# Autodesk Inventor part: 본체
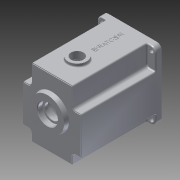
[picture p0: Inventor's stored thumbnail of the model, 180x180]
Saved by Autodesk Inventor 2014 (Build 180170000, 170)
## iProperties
Created: 2016-02
Part Number: 본체
Material: 알루미늄 6061
Document SubType Name: Modeling
Designer: mduedu
Density: 2.71 g/cm^3
Appearance: 알루미늄 - 평지
Author: mduedu
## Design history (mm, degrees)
sketch "스케치1"
  geometry: L1 (-47, -47)-(47, -47); L2 (47, -47)-(47, 63); L3 (47, 63)-(-47, 63); L4 (-47, 63)-(-47, -47); 2 further points
  constraints: 8 end point, 2 parallel, 1 horizontal, 1 midpoint, 1 perpendicular, 1 vertical alignment
  dimensions: "d0" = 94 distance of L2.end L3.end; "d155" = 110 distance of L1.end L2.end; "d156" = 47 distance from line of L1 point (0, 0)
extrude "돌출1" new body sketch "스케치1" distance "d2" = 130; taper "d3" = 0 deg
sketch "스케치3"
  geometry: C1 r 40 at (0, 0); 1 further point
  constraints: 1 centre point, 1 coincident
  dimensions: "d9" = 80 diameter of C1
extrude "돌출3" cut sketch "스케치3" distance "d11" = 121; taper "d12" = 0 deg
sketch "스케치4"
  geometry: C1 r 21 at (0, 11); 1 further point
  constraints: 1 centre point, 1 vertical alignment
  dimensions: "d13" = 21 radius of C1; "d15" = 11 distance of point (0, 0) C1.centre
extrude "돌출4" join sketch "스케치4" distance "d16" = 7; taper "d17" = 0 deg
sketch "스케치5"
  geometry: C1 r 15 at (0, -20); 1 further point
  constraints: 1 centre point, 1 vertical alignment
  dimensions: "d18" = 15 radius of C1; "d20" = 20 distance of point (0, 0) C1.centre
extrude "돌출5" join sketch "스케치5" distance "d21" = 7; taper "d22" = 0 deg
sketch "스케치6"
  geometry: C1 r 28 at (0, 11); A1 r 21 centre (0, 11) between (8.978, -7.984) and (-8.978, -7.984) reference; 1 further point
  constraints: 1 centre point, 1 coincident
  dimensions: "d23" = 56 diameter of C1
extrude "돌출6" join sketch "스케치6" distance "d25" = 7; taper "d26" = -10 deg
hole "구멍1" diameter "d29" = 35; stored, may be unused: countersink angle "d33" = 90 deg, drill point angle "d35" = 0 deg; dims "d27" = 10, "d28" = 10, "d30" = 6, "d31" = 4, "d32" = 2, "d34" = 10
hole "구멍2" diameter "d38" = 22; stored, may be unused: countersink angle "d42" = 90 deg, drill point angle "d44" = 0 deg; dims "d36" = 10, "d37" = 10, "d39" = 6, "d40" = 4, "d41" = 2, "d43" = 7
hole "구멍3" diameter "d47" = 19; stored, may be unused: countersink angle "d51" = 90 deg, drill point angle "d53" = 0 deg; dims "d45" = 10, "d46" = 10, "d48" = 6, "d49" = 4, "d50" = 2, "d52" = 1
hole "구멍4" diameter "d56" = 32; stored, may be unused: countersink angle "d60" = 90 deg, drill point angle "d62" = 0 deg; dims "d54" = 10, "d55" = 10, "d57" = 6, "d58" = 4, "d59" = 2, "d61" = 8
hole "구멍5" diameter "d65" = 25; stored, may be unused: countersink angle "d69" = 90 deg, drill point angle "d71" = 0 deg; dims "d63" = 10, "d64" = 10, "d66" = 6, "d67" = 4, "d68" = 2, "d70" = 8
fillet "모깎기2" dims "d73" = 0.3
fillet "모깎기3" dims "d74" = 2
chamfer "모따기1" distance "d75" = 1; stored, may be unused: second distance "d76" = 2, angle "d77" = 45 deg
fillet "모깎기4" dims "d78" = 3
sketch "스케치16"
  geometry: L1 (-23, 32.726)-(23, 32.726); L2 (23, 32.726)-(23, 53); L3 (23, 53)-(-23, 53); L4 (-23, 53)-(-23, 32.726); L5 (-47, 63)-(47, 63) reference; 3 further points
  constraints: 8 end point, 2 parallel, 1 horizontal, 1 midpoint, 1 perpendicular, 1 vertical alignment, 2 other
  dimensions: "d160" = 46 distance of L2.end L3.end; "d163" = 10 distance between parallel lines of L3 L5
extrude "돌출15" cut sketch "스케치16" stored distance "d164" = 10; taper "d165" = 0 deg
fillet "모깎기5" dims "d79" = 2
fillet "모깎기15" dims "d166" = 5
sketch "스케치7"
  geometry: L1 (-23, 48)-(-23, 35.228) reference; L2 (23, 35.228)-(23, 48) reference; L3 (18, 53)-(-18, 53) reference; L4 (47, 63)-(47, -47) reference; L5 (47, -47)-(-47, -47) reference; L6 (-47, -47)-(-47, 63) reference; L7 (-47, 63)-(47, 63) reference; L8 (-26, 48)-(-26, 35.228); L9 (26, 35.228)-(26, 48); L10 (18, 56)-(-18, 56); C1 r 43 at (0, 0); A1 r 5 centre (-18, 48) between (-18, 53) and (-23, 48) reference; A2 r 5 centre (-28, 35.228) between (-24.889, 31.314) and (-23, 35.228) reference; A3 r 40 centre (0, 0) between (-24.889, 31.314) and (24.889, 31.314) reference; A4 r 5 centre (28, 35.228) between (23, 35.228) and (24.889, 31.314) reference; A5 r 5 centre (18, 48) between (23, 48) and (18, 53) reference; A6 r 8 centre (-18, 48) between (-18, 56) and (-26, 48); A7 r 2 centre (-28, 35.228) between (-26.756, 33.662) and (-26, 35.228); A8 r 43 centre (0, 0) between (-26.756, 33.662) and (26.756, 33.662); A9 r 2 centre (28, 35.228) between (26, 35.228) and (26.756, 33.662); A10 r 8 centre (18, 48) between (26, 48) and (18, 56); 1 further point
  constraints: 10 point on circle, 6 centre point, 6 end point, 1 coincident, 7 other
  dimensions: "d80" = 86 diameter of C1; "d167" = 3 distance between parallel lines of L3 L10
extrude "돌출7" cut sketch "스케치7" distance "d83" = 9; taper "d84" = 0 deg
sketch "스케치8" dims "d168" = 36
  geometry: L1 (-36, 4)-(-39.799, 4); L2 (-36, -4)-(-39.799, -4); A1 r 4 centre (-36, 0) between (-36, 4) and (-36, -4); A2 r 40 centre (0, 0) between (-24.889, 31.314) and (24.889, 31.314) reference; A3 r 40 centre (0, 0) between (-39.799, 4) and (-39.799, -4); 2 further points
  constraints: 5 point on circle, 4 end point, 2 centre point, 2 coincident, 2 horizontal alignment, 2 tangent, 1 horizontal, 1 parallel, 2 other
  dimensions: "d169" = 4 radius of A1
extrude "돌출9" join sketch "스케치8" stored distance "d89" = 9; taper "d90" = 0 deg
fillet "모깎기6" dims "d91" = 3.5
sketch "스케치9"
  geometry: L1 (47, 63)-(-47, 63) reference; L2 (47, -47)-(47, 63) reference; L3 (47, 63)-(33, 63); L4 (33, 63)-(33, 30); L5 (33, 30)-(47, 30); L6 (47, 30)-(47, 63); 2 further points
  constraints: 8 end point, 2 parallel, 1 horizontal, 1 perpendicular
  dimensions: "d95" = 33 distance from line of L4 point (0, 0); "d96" = 30 distance from line of L5 point (0, 0)
extrude "돌출10" cut sketch "스케치9" distance "d97" = 120; taper "d98" = 0 deg
sketch "스케치11"
  geometry: L1 (-40, -40)-(40, -40); L2 (40, -40)-(40, 56); L3 (40, 56)-(-40, 56); L4 (-40, 56)-(-40, -40); L5 (-47, -47)-(47, -47) reference; L6 (47, 63)-(-47, 63) reference; L7 (-47, 63)-(-47, -47) reference; C1 r 3.5 at (-40, 56); C2 r 3.5 at (40, 56); C3 r 3.5 at (40, -40); C4 r 3.5 at (-40, -40); 1 further point
  constraints: 8 end point, 4 centre point, 4 coincident, 3 equal radius, 2 parallel, 1 horizontal, 1 perpendicular
  dimensions: "d109" = 80 distance of L2.end L3.end; "d112" = 7 diameter of C1; "d157" = 7 distance from line of L1.start L5; "d158" = 7 distance between parallel lines of L6 L3; "d159" = 7 distance from line of L7 L3.end
extrude "돌출12" cut sketch "스케치11" stored distance "d113" = 63; taper "d114" = 0 deg
fillet "모깎기7" dims "d115" = 8
fillet "모깎기8" dims "d116" = 5
fillet "모깎기11" dims "d119" = 2
fillet "모깎기12" dims "d120" = 2
fillet "모깎기13" dims "d121" = 2
sketch "스케치12"
  geometry: 3 further points
  constraints: 2 horizontal alignment
hole "구멍6" sketch "스케치12" at (36, 0), (-36, 0) diameter "d122" = 3.242; stored, may be unused: countersink angle "d126" = 90 deg, drill point angle "d128" = 120 deg; dims "d123" = 7, "d124" = 4, "d125" = 2, "d127" = 9
sketch "스케치13"
  geometry: L1 (-33, 35)-(-33, 61) reference; L2 (-31, 63)-(31, 63) reference; L3 (33, 61)-(33, 35) reference; L4 (33, -35)-(33, -45) reference; L5 (31, -47)-(-31, -47) reference; L6 (-33, -45)-(-33, -35) reference; L7 (38, 30)-(45, 30) reference; L8 (47, 28)-(47, -28) reference; L9 (45, -30)-(38, -30) reference; L10 (-38, -30)-(-45, -30) reference; L11 (-47, -28)-(-47, 28) reference; L12 (-45, 30)-(-38, 30) reference; L13 (31, 62)-(-31, 62); L14 (-32, 61)-(-32, 35); L15 (-38, 29)-(-45, 29); L16 (-46, 28)-(-46, -28); L17 (-45, -29)-(-38, -29); L18 (-32, -35)-(-32, -45); L19 (-31, -46)-(31, -46); L20 (32, -45)-(32, -35); L21 (38, -29)-(45, -29); L22 (46, -28)-(46, 28); L23 (45, 29)-(38, 29); L24 (32, 35)-(32, 61); L25 (38, 30)-(45, 30) reference; L26 (47, 28)-(47, -28) reference; L27 (45, -30)-(38, -30) reference; L28 (33, -35)-(33, -45) reference; L29 (31, -47)-(-31, -47) reference; L30 (-33, -45)-(-33, -35) reference; L31 (-38, -30)-(-45, -30) reference; L32 (-47, -28)-(-47, 28) reference; L33 (-45, 30)-(-38, 30) reference; L34 (-33, 35)-(-33, 61) reference; L35 (33, 61)-(33, 35) reference; L36 (-31, 63)-(31, 63) reference; C1 r 16 at (0, 11) reference; C2 r 28 at (0, 11) reference; C3 r 16 at (0, 11) reference; C4 r 28 at (0, 11) reference; A1 r 5 centre (-38, 35) between (-38, 30) and (-33, 35) reference; A2 r 2 centre (-31, 61) between (-31, 63) and (-33, 61) reference; A3 r 2 centre (31, 61) between (33, 61) and (31, 63) reference; A4 r 5 centre (38, 35) between (33, 35) and (38, 30) reference; A5 r 5 centre (38, -35) between (38, -30) and (33, -35) reference; A6 r 2 centre (31, -45) between (31, -47) and (33, -45) reference; A7 r 2 centre (-31, -45) between (-33, -45) and (-31, -47) reference; A8 r 5 centre (-38, -35) between (-33, -35) and (-38, -30) reference; A9 r 2 centre (45, 28) between (47, 28) and (45, 30) reference; A10 r 2 centre (45, -28) between (45, -30) and (47, -28) reference; A11 r 2 centre (-45, -28) between (-47, -28) and (-45, -30) reference; A12 r 2 centre (-45, 28) between (-45, 30) and (-47, 28) reference; A13 r 1 centre (-31, 61) between (-31, 62) and (-32, 61); A14 r 6 centre (-38, 35) between (-38, 29) and (-32, 35); A15 r 1 centre (-45, 28) between (-45, 29) and (-46, 28); A16 r 1 centre (-45, -28) between (-46, -28) and (-45, -29); A17 r 6 centre (-38, -35) between (-32, -35) and (-38, -29); A18 r 1 centre (-31, -45) between (-32, -45) and (-31, -46); A19 r 1 centre (31, -45) between (31, -46) and (32, -45); A20 r 6 centre (38, -35) between (38, -29) and (32, -35); A21 r 1 centre (45, -28) between (45, -29) and (46, -28); A22 r 1 centre (45, 28) between (46, 28) and (45, 29); A23 r 6 centre (38, 35) between (32, 35) and (38, 29); A24 r 1 centre (31, 61) between (32, 61) and (31, 62); A25 r 5 centre (38, 35) between (33, 35) and (38, 30) reference; A26 r 2 centre (45, 28) between (47, 28) and (45, 30) reference; A27 r 2 centre (45, -28) between (45, -30) and (47, -28) reference; A28 r 5 centre (38, -35) between (38, -30) and (33, -35) reference; A29 r 2 centre (31, -45) between (31, -47) and (33, -45) reference; A30 r 2 centre (-31, -45) between (-33, -45) and (-31, -47) reference; A31 r 5 centre (-38, -35) between (-33, -35) and (-38, -30) reference; A32 r 2 centre (-45, -28) between (-47, -28) and (-45, -30) reference; A33 r 2 centre (-45, 28) between (-45, 30) and (-47, 28) reference; A34 r 5 centre (-38, 35) between (-38, 30) and (-33, 35) reference; A35 r 2 centre (-31, 61) between (-31, 63) and (-33, 61) reference; A36 r 2 centre (31, 61) between (33, 61) and (31, 63) reference
  constraints: 24 end point, 24 point on circle, 12 centre point, 23 other
  dimensions: "d154" = 1 distance between parallel lines of L13 L2
extrude "돌출13" cut sketch "스케치13" distance "d130" = 1; taper "d131" = 0 deg
fillet "모깎기14" dims "d147" = 0.3
sketch "스케치15"
  geometry: L1 (78, 0)-(0, 0) reference; 3 further points
  constraints: 1 midpoint, 1 vertical alignment, 1 other
  dimensions: "d148" = 40 distance of point (39, -40) point (39, 0)
feature "엠보싱1" sketch "스케치15" dims "d22" = 0, "d149" = 0.5, "d150" = 0
chamfer "모따기4" distance "d151" = 1; stored, may be unused: second distance "d152" = 2, angle "d153" = 45 deg
sketch "스케치17"
  geometry: L1 (39.004, -17.213)-(39.004, -18.809) reference; L2 (39.004, -18.809)-(38.548, -18.809) reference; L3 (38.548, -18.809)-(38.548, -17.213) reference; L4 (38.548, -17.213)-(35.455, -17.213) reference; L5 (35.455, -17.213)-(35.455, -16.822) reference; L6 (35.772, -16.659)-(42.578, -16.659) reference; L7 (42.578, -16.659)-(42.578, -17.213) reference; L8 (42.578, -17.213)-(39.004, -17.213) reference; L9 (38.223, -56.73)-(38.695, -56.73) reference; L10 (38.695, -56.73)-(38.695, -58.073) reference; L11 (38.695, -58.073)-(40.787, -58.073) reference; L12 (40.787, -58.073)-(40.787, -58.643) reference; L13 (40.787, -58.643)-(35.398, -58.643) reference; L14 (35.398, -58.643)-(35.398, -58.277) reference; L15 (35.715, -58.073)-(38.223, -58.073) reference; L16 (38.223, -58.073)-(38.223, -56.73) reference; L17 (41.927, -57.813)-(42.383, -57.813) reference; L18 (42.383, -57.813)-(42.383, -63.031) reference; L19 (42.383, -63.031)-(40.429, -63.031) reference; L20 (40.429, -63.031)-(40.429, -62.608) reference; L21 (40.689, -62.478)-(41.927, -62.478) reference; L22 (41.927, -62.478)-(41.927, -57.813) reference; L23 (36.09, -60.849)-(36.09, -62.624) reference; L24 (36.09, -62.624)-(35.666, -62.624) reference; L25 (35.666, -62.624)-(35.666, -60.849) reference; L26 (35.666, -60.849)-(36.09, -60.849) reference; L27 (37.058, -64.057)-(36.635, -64.057) reference; L28 (36.635, -64.057)-(36.635, -59.539) reference; L29 (36.635, -59.539)-(37.058, -59.539) reference; L30 (37.058, -59.539)-(37.058, -64.057) reference; L31 (42.138, -43.501)-(40.307, -44.168) reference; L32 (40.307, -44.168)-(40.307, -46.871) reference; L33 (40.307, -46.871)-(42.138, -47.555) reference; L34 (42.138, -47.555)-(42.138, -48.133) reference; L35 (42.138, -48.133)-(36.138, -45.853) reference; L36 (36.138, -45.853)-(36.138, -45.202) reference; L37 (36.138, -45.202)-(42.138, -42.923) reference; L38 (42.138, -42.923)-(42.138, -43.501) reference; L39 (36.725, -45.536)-(39.81, -46.684) reference; L40 (39.81, -46.684)-(39.81, -44.364) reference; L41 (39.81, -44.364)-(36.725, -45.536) reference; L42 (40.022, -52.114)-(40.022, -49.94) reference; L43 (40.022, -49.94)-(42.57, -49.94) reference; L44 (42.57, -49.94)-(42.57, -50.494) reference; L45 (42.57, -50.494)-(40.469, -50.494) reference; L46 (40.469, -50.494)-(40.469, -55.094) reference; L47 (40.469, -55.094)-(40.022, -55.094) reference; L48 (40.022, -55.094)-(40.022, -52.659) reference; L49 (40.022, -52.659)-(38.556, -52.659) reference; L50 (38.556, -52.659)-(38.556, -55.973) reference; L51 (38.556, -55.973)-(38.109, -55.973) reference; L52 (38.109, -55.973)-(38.109, -50.73) reference; L53 (36.106, -50.388)-(36.106, -54.955) reference; L54 (36.106, -54.955)-(35.65, -54.955) reference; L55 (35.65, -54.955)-(35.65, -49.81) reference; L56 (38.109, -50.136)-(38.109, -48.768) reference; L57 (38.109, -48.768)-(38.556, -48.768) reference; L58 (38.556, -48.768)-(38.556, -52.114) reference; L59 (38.556, -52.114)-(40.022, -52.114) reference; L60 (36.138, -38.168)-(36.635, -38.168) reference; L61 (36.635, -38.168)-(36.635, -40.041) reference; L62 (36.635, -40.041)-(42.138, -40.041) reference; L63 (42.138, -40.041)-(42.138, -40.586) reference; L64 (42.138, -40.586)-(36.635, -40.586) reference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; C1 r 10 at (39, -89); A1 r 4 centre (4, -12) between (8, -12) and (4, -8) reference; A2 r 4 centre (74, -12) between (74, -8) and (70, -12) reference; 61 further points
  constraints: 2 end point, 1 centre point, 1 midpoint, 1 point on line, 76 other
  dimensions: "d170" = 20 diameter of C1; "d171" = 41 distance from line of C1.centre L110
extrude "돌출16" cut sketch "스케치17" stored distance "d172" = 10; taper "d173" = 0 deg
sketch "스케치18"
  geometry: C1 r 10 at (39, -89) reference; C2 r 15 at (39, -89); 1 further point
  constraints: 1 centre point, 1 coincident
  dimensions: "d174" = 30 diameter of C2
extrude "돌출17" join sketch "스케치18" distance "d175" = 5; taper "d176" = 0 deg
fillet "모깎기16" dims "d177" = 2
sketch "스케치19"
  geometry: C1 r 10 at (18, 80) reference; C2 r 15 at (18, 80); 1 further point
  constraints: 1 centre point, 1 coincident
  dimensions: "d178" = 30 diameter of C2
extrude "돌출18" cut sketch "스케치19" distance "d181" = 5; taper "d182" = 0 deg
chamfer "모따기5" distance "d183" = 0.5; stored, may be unused: second distance "d184" = 2, angle "d185" = 45 deg
node "솔리드1"
pattern_circular "원형 패턴1" dims angle "d93" = 360 deg
mirror "대칭1"
mirror "대칭2"
node "절단 모서리 투영1"
node "절단 모서리 투영2"
node "절단 모서리 투영3"
node "절단 모서리 투영4"
